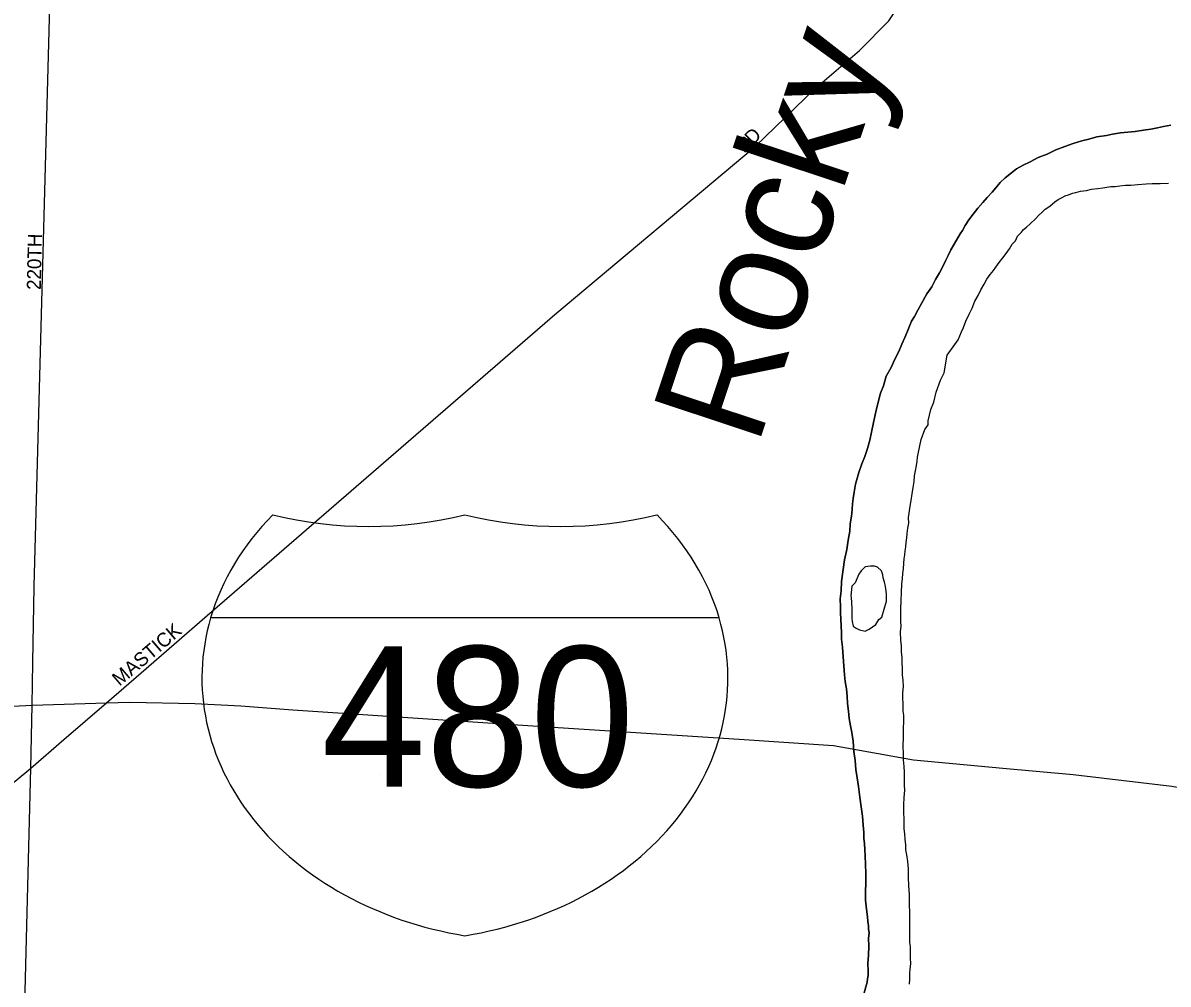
# Model space of a CAD drawing. Extents: x -561 to 1170, y 0 to 846.
# Drawn here: x 115.96 to 126.99, y 211.77 to 221.02 of the extents above; entities that cross this region are included whole.
import ezdxf

# ---------------------------------------------------------------- set-up
doc = ezdxf.new("R2010")
doc.units = 0
for name, color, linetype in [('GM_X_City_Street', 7, 'Continuous'), ('GM_X_City_Street_Text', 7, 'Continuous'), ('GM_X_Interstate_Location', 7, 'Continuous'), ('GM_X_Interstate_Route', 7, 'Continuous'), ('GM_X_Interstate_Shield', 7, 'Continuous'), ('GM_X_Major_River', 7, 'Continuous'), ('GM_X_Major_River_Text', 7, 'Continuous')]:
    doc.layers.add(name, color=color, linetype=linetype)

msp = doc.modelspace()

# ---------------------------------------------------------------- linework, layer by layer
at = {"layer": 'GM_X_City_Street'}
for points in [[(116.071, 215.595), (116.452, 229.741), (116.491, 231.039), (116.448, 231.209)], [(117.737, 215.314), (121.082, 218.211), (123.012, 219.827), (123.587, 220.387), (124.016, 220.753), (124.298, 221.039), (124.521, 221.379), (124.761, 221.789), (125.169, 222.415), (125.485, 222.833), (125.94, 223.24), (126.531, 223.757), (126.787, 223.943)], [(116.057, 214.865), (116.071, 215.589), (116.071, 215.595)], [(117.1, 214.762), (117.737, 215.314), (117.737, 215.314)], [(116.038, 213.843), (116.05, 214.449), (116.057, 214.861), (116.057, 214.865)], [(116.357, 214.118), (116.766, 214.473), (117.1, 214.762), (117.1, 214.762)], [(116.038, 213.843), (116.357, 214.118), (116.357, 214.118)], [(107.912, 208.655), (108.898, 209.185), (109.975, 209.776), (111.966, 210.908), (113.048, 211.474), (113.955, 212.017), (115.111, 212.997), (115.886, 213.719), (116.038, 213.843)], [(115.967, 211.064), (116.038, 213.843)]]:
    msp.add_lwpolyline(points, dxfattribs=at)
at = {"layer": 'GM_X_Interstate_Route'}
for points in [[(109.61, 213.187), (109.745, 213.235), (110.052, 213.346), (111.576, 213.815), (112.111, 213.979), (112.489, 214.094), (112.787, 214.155), (113.084, 214.194), (113.425, 214.244), (113.863, 214.289), (114.382, 214.334), (115.242, 214.408), (116.05, 214.449), (116.766, 214.473), (116.99, 214.48), (117.617, 214.465), (118.061, 214.445), (118.559, 214.404), (121.014, 214.243)], [(121.014, 214.243), (122.857, 214.122)], [(122.857, 214.122), (123.765, 214.062), (124.534, 213.923), (125.396, 213.844)], [(125.396, 213.844), (126.072, 213.782), (127.02, 213.67), (127.943, 213.499), (128.481, 213.369), (129.006, 213.216), (129.464, 213.053), (130.319, 212.721), (132.188, 211.906)]]:
    msp.add_lwpolyline(points, dxfattribs=at)
at = {"layer": 'GM_X_Interstate_Shield'}
msp.add_line((122.664, 215.29), (117.769, 215.29), dxfattribs=at)
msp.add_line((122.664, 215.29), (117.769, 215.29), dxfattribs=at)
for centre, start_param, end_param in [((120.849, 214.711), 2.47259, 2.911027), ((119.292, 218.702), 4.415841, 5.008937), ((121.141, 218.702), 4.415841, 5.008937), ((119.584, 214.711), 0.230566, 0.669003), ((120.849, 214.711), 2.911027, 4.511031), ((119.584, 214.711), 4.913747, 6.513751)]:
    msp.add_ellipse(centre, major_axis=(3.164, 0), ratio=0.8, start_param=start_param, end_param=end_param, dxfattribs=at)
at = {"layer": 'GM_X_Major_River'}
for points in [[(124.544, 218.192), (124.575, 218.252), (124.612, 218.318), (124.664, 218.411), (124.712, 218.477), (124.748, 218.548), (124.785, 218.613), (124.816, 218.674), (124.843, 218.728), (124.869, 218.778), (124.895, 218.832), (124.926, 218.887), (124.984, 218.986), (125.005, 219.019), (125.031, 219.068), (125.068, 219.123), (125.11, 219.178), (125.153, 219.233), (125.201, 219.288), (125.243, 219.338), (125.291, 219.387), (125.328, 219.431), (125.37, 219.481), (125.418, 219.525), (125.477, 219.575), (125.525, 219.614), (125.589, 219.648), (125.659, 219.681), (125.734, 219.721), (125.82, 219.755), (125.906, 219.795), (125.992, 219.829), (126.073, 219.857), (126.154, 219.881), (126.224, 219.898), (126.299, 219.921), (126.391, 219.934), (126.451, 219.946), (126.526, 219.958), (126.597, 219.965), (126.667, 219.972), (126.748, 219.984), (126.818, 219.996), (126.883, 220.008), (126.942, 220.02), (127.013, 220.033)], [(127.013, 220.033), (126.942, 220.02), (126.883, 220.008), (126.818, 219.996), (126.748, 219.984), (126.667, 219.972), (126.597, 219.965), (126.526, 219.958), (126.451, 219.946), (126.391, 219.934), (126.299, 219.921), (126.224, 219.898), (126.154, 219.881), (126.073, 219.857), (125.992, 219.829), (125.906, 219.795), (125.82, 219.755), (125.734, 219.721), (125.659, 219.681), (125.589, 219.648), (125.525, 219.614), (125.477, 219.575), (125.418, 219.525), (125.37, 219.481), (125.328, 219.431), (125.291, 219.387), (125.243, 219.338), (125.201, 219.288), (125.153, 219.233), (125.11, 219.178), (125.068, 219.123), (125.031, 219.068), (125.005, 219.019), (124.984, 218.986), (124.926, 218.887), (124.895, 218.832), (124.869, 218.778), (124.843, 218.728), (124.816, 218.674), (124.785, 218.613), (124.748, 218.548), (124.712, 218.477), (124.664, 218.411), (124.612, 218.318), (124.575, 218.252), (124.544, 218.192)], [(124.439, 213.925), (124.438, 213.985), (124.436, 214.055), (124.44, 214.142), (124.439, 214.223), (124.443, 214.299), (124.442, 214.353), (124.436, 214.391), (124.435, 214.418), (124.434, 214.467), (124.433, 214.516), (124.432, 214.57), (124.437, 214.629), (124.436, 214.689), (124.429, 214.743), (124.428, 214.803), (124.427, 214.857), (124.426, 214.906), (124.42, 214.965), (124.418, 215.025), (124.412, 215.073), (124.411, 215.155), (124.415, 215.209), (124.414, 215.252), (124.413, 215.306), (124.412, 215.377), (124.424, 215.615), (124.428, 215.67), (124.433, 215.719), (124.437, 215.762), (124.442, 215.816), (124.446, 215.86), (124.451, 215.898), (124.456, 215.936), (124.46, 215.974), (124.465, 216.017), (124.47, 216.061), (124.474, 216.104), (124.479, 216.153), (124.489, 216.202), (124.488, 216.256), (124.492, 216.299), (124.502, 216.365), (124.512, 216.419), (124.521, 216.484), (124.531, 216.544), (124.541, 216.604), (124.545, 216.658), (124.555, 216.707), (124.565, 216.756), (124.57, 216.799), (124.574, 216.837), (124.579, 216.87), (124.609, 217.006), (124.645, 217.104), (124.677, 217.148), (124.676, 217.186), (124.701, 217.295), (124.732, 217.366), (124.752, 217.464), (124.794, 217.579), (124.83, 217.65), (124.859, 217.818), (124.933, 217.923), (124.965, 217.967), (124.981, 218.005), (124.996, 218.043), (125.017, 218.087), (125.038, 218.147), (125.069, 218.213), (125.1, 218.273), (125.126, 218.338), (125.158, 218.393), (125.184, 218.448), (125.215, 218.502), (125.241, 218.552), (125.273, 218.596), (125.305, 218.634), (125.326, 218.667), (125.358, 218.711), (125.395, 218.755), (125.426, 218.799), (125.458, 218.843), (125.484, 218.887), (125.516, 218.92), (125.537, 218.964), (125.574, 219.003), (125.595, 219.03), (125.622, 219.052), (125.659, 219.085), (125.713, 219.135), (125.739, 219.163), (125.771, 219.191), (125.803, 219.224), (125.846, 219.252), (125.894, 219.296), (125.926, 219.318), (125.953, 219.329), (126.001, 219.357), (126.028, 219.363), (126.066, 219.38)], [(124.439, 213.925), (124.438, 213.985), (124.436, 214.055), (124.44, 214.142), (124.439, 214.223), (124.443, 214.299), (124.442, 214.353), (124.436, 214.391), (124.435, 214.418), (124.434, 214.467), (124.433, 214.516), (124.432, 214.57), (124.437, 214.629), (124.436, 214.689), (124.429, 214.743), (124.428, 214.803), (124.427, 214.857), (124.426, 214.906), (124.42, 214.965), (124.418, 215.025), (124.412, 215.073), (124.411, 215.155), (124.415, 215.209), (124.414, 215.252), (124.413, 215.306), (124.412, 215.377), (124.424, 215.615), (124.428, 215.67), (124.433, 215.719), (124.437, 215.762), (124.442, 215.816), (124.446, 215.86), (124.451, 215.898), (124.456, 215.936), (124.46, 215.974), (124.465, 216.017), (124.47, 216.061), (124.474, 216.104), (124.479, 216.153), (124.489, 216.202), (124.488, 216.256), (124.492, 216.299), (124.502, 216.365), (124.512, 216.419), (124.521, 216.484), (124.531, 216.544), (124.541, 216.604), (124.545, 216.658), (124.555, 216.707), (124.565, 216.756), (124.57, 216.799), (124.574, 216.837), (124.579, 216.87), (124.609, 217.006), (124.645, 217.104), (124.677, 217.148), (124.676, 217.186), (124.701, 217.295), (124.732, 217.366), (124.752, 217.464), (124.794, 217.579), (124.83, 217.65), (124.859, 217.818), (124.933, 217.923), (124.965, 217.967), (124.981, 218.005), (124.996, 218.043), (125.017, 218.087), (125.038, 218.147), (125.069, 218.213), (125.1, 218.273), (125.126, 218.338), (125.158, 218.393), (125.184, 218.448), (125.215, 218.502), (125.241, 218.552), (125.273, 218.596), (125.305, 218.634), (125.326, 218.667), (125.358, 218.711), (125.395, 218.755), (125.426, 218.799), (125.458, 218.843), (125.484, 218.887), (125.516, 218.92), (125.537, 218.964), (125.574, 219.003), (125.595, 219.03), (125.622, 219.052), (125.659, 219.085), (125.713, 219.135), (125.739, 219.163), (125.771, 219.191), (125.803, 219.224), (125.846, 219.252), (125.894, 219.296), (125.926, 219.318), (125.953, 219.329), (126.001, 219.357), (126.028, 219.363), (126.066, 219.38)], [(126.066, 219.38), (126.098, 219.386), (126.141, 219.398), (126.201, 219.405), (126.249, 219.416), (126.309, 219.423), (126.357, 219.429), (126.395, 219.436), (126.433, 219.442), (126.476, 219.442), (126.52, 219.449), (126.574, 219.455), (126.628, 219.456), (126.693, 219.463), (126.774, 219.47), (126.833, 219.471), (126.909, 219.472), (126.991, 219.474)], [(126.066, 219.38), (126.098, 219.386), (126.141, 219.398), (126.201, 219.405), (126.249, 219.416), (126.309, 219.423), (126.357, 219.429), (126.395, 219.436), (126.433, 219.442), (126.476, 219.442), (126.52, 219.449), (126.574, 219.455), (126.628, 219.456), (126.693, 219.463), (126.774, 219.47), (126.833, 219.471), (126.909, 219.472), (126.991, 219.474)], [(124.053, 211.658), (124.089, 211.783), (124.093, 211.816), (124.098, 211.849), (124.097, 211.892), (124.096, 211.962), (124.1, 212.044), (124.104, 212.13), (124.102, 212.206), (124.107, 212.255), (124.101, 212.298), (124.1, 212.325), (124.094, 212.369), (124.093, 212.412), (124.087, 212.461), (124.08, 212.515), (124.074, 212.574), (124.072, 212.655), (124.076, 212.737), (124.075, 212.829), (124.073, 212.921), (124.071, 212.997), (124.065, 213.062), (124.064, 213.116), (124.057, 213.17), (124.056, 213.224), (124.05, 213.294), (124.043, 213.381), (124.03, 213.473), (124.018, 213.565), (124.005, 213.667), (123.992, 213.749), (123.98, 213.83), (123.973, 213.916), (123.961, 214.003), (123.953, 214.105), (123.941, 214.186), (123.929, 214.251), (123.917, 214.321), (123.91, 214.392), (123.898, 214.467), (123.897, 214.538), (123.89, 214.608), (123.878, 214.678), (123.871, 214.743), (123.864, 214.83), (123.857, 214.916), (123.85, 215.008), (123.843, 215.084), (123.842, 215.149), (123.833, 215.339), (123.832, 215.398), (123.83, 215.474), (123.84, 215.55), (123.843, 215.642), (123.872, 215.849), (123.892, 215.947), (123.906, 216.039), (123.921, 216.126), (123.925, 216.196), (123.935, 216.251), (123.94, 216.294), (123.944, 216.338), (123.949, 216.387), (123.953, 216.441), (123.963, 216.501), (123.978, 216.577), (124.008, 216.691), (124.039, 216.773), (124.065, 216.844), (124.091, 216.92), (124.116, 217.002), (124.131, 217.078), (124.151, 217.171), (124.171, 217.274), (124.196, 217.367), (124.216, 217.454), (124.247, 217.525), (124.273, 217.617), (124.32, 217.7), (124.356, 217.782), (124.393, 217.853), (124.424, 217.924), (124.45, 217.989), (124.476, 218.049), (124.497, 218.099), (124.517, 218.148), (124.544, 218.192)], [(124.544, 218.192), (124.517, 218.148), (124.497, 218.099), (124.476, 218.049), (124.45, 217.989), (124.424, 217.924), (124.393, 217.853), (124.356, 217.782), (124.32, 217.7), (124.273, 217.617), (124.247, 217.525), (124.216, 217.454), (124.196, 217.367), (124.171, 217.274), (124.151, 217.171), (124.131, 217.078), (124.116, 217.002), (124.091, 216.92), (124.065, 216.844), (124.039, 216.773), (124.008, 216.691), (123.978, 216.577), (123.963, 216.501), (123.953, 216.441), (123.949, 216.387), (123.944, 216.338), (123.94, 216.294), (123.935, 216.251), (123.925, 216.196), (123.921, 216.126), (123.906, 216.039), (123.892, 215.947), (123.872, 215.849), (123.843, 215.642), (123.84, 215.55), (123.83, 215.474), (123.832, 215.398), (123.833, 215.339), (123.842, 215.149), (123.843, 215.084), (123.85, 215.008), (123.857, 214.916), (123.864, 214.83), (123.871, 214.743), (123.878, 214.678), (123.89, 214.608), (123.897, 214.538), (123.898, 214.467), (123.91, 214.392), (123.917, 214.321), (123.929, 214.251), (123.941, 214.186), (123.953, 214.105), (123.961, 214.003), (123.973, 213.916), (123.98, 213.83), (123.992, 213.749), (124.005, 213.667), (124.018, 213.565), (124.03, 213.473), (124.043, 213.381), (124.05, 213.294), (124.056, 213.224), (124.057, 213.17), (124.064, 213.116), (124.065, 213.062), (124.071, 212.997), (124.073, 212.921), (124.075, 212.829), (124.076, 212.737), (124.072, 212.655), (124.074, 212.574), (124.08, 212.515), (124.087, 212.461), (124.093, 212.412), (124.094, 212.369), (124.1, 212.325), (124.101, 212.298), (124.107, 212.255), (124.102, 212.206), (124.104, 212.13), (124.1, 212.044), (124.096, 211.962), (124.097, 211.892), (124.098, 211.849), (124.093, 211.816), (124.089, 211.783), (124.053, 211.658)], [(124.068, 215.782), (124.031, 215.743), (124.01, 215.71), (123.974, 215.628), (123.942, 215.595), (123.933, 215.503), (123.934, 215.49)], [(124.068, 215.782), (124.031, 215.743), (124.01, 215.71), (123.974, 215.628), (123.942, 215.595), (123.933, 215.503), (123.934, 215.49)], [(123.934, 215.49), (123.94, 215.379), (123.941, 215.33), (123.942, 215.286), (123.943, 215.254), (123.954, 215.211), (123.982, 215.19), (124.015, 215.174), (124.069, 215.164), (124.107, 215.181), (124.139, 215.204), (124.171, 215.226), (124.202, 215.275), (124.229, 215.297), (124.275, 215.45), (124.274, 215.52), (124.267, 215.574), (124.261, 215.607), (124.255, 215.634), (124.244, 215.677), (124.238, 215.704), (124.226, 215.742), (124.188, 215.779), (124.16, 215.789), (124.122, 215.788), (124.068, 215.782)], [(123.934, 215.49), (123.94, 215.379), (123.941, 215.33), (123.942, 215.286), (123.943, 215.254), (123.954, 215.211), (123.982, 215.19), (124.015, 215.174), (124.069, 215.164), (124.107, 215.181), (124.139, 215.204), (124.171, 215.226), (124.202, 215.275), (124.229, 215.297), (124.275, 215.45), (124.274, 215.52), (124.267, 215.574), (124.261, 215.607), (124.255, 215.634), (124.244, 215.677), (124.238, 215.704), (124.226, 215.742), (124.188, 215.779), (124.16, 215.789), (124.122, 215.788), (124.068, 215.782)], [(124.026, 215.77), (124.025, 215.77)], [(124.026, 215.77), (124.025, 215.77)], [(124.495, 211.764), (124.5, 211.813), (124.499, 211.867), (124.503, 211.911), (124.508, 211.959), (124.507, 212.019), (124.506, 212.073), (124.505, 212.127), (124.499, 212.165), (124.498, 212.203), (124.499, 212.447), (124.497, 212.539), (124.496, 212.626), (124.489, 212.712), (124.487, 212.793), (124.486, 212.875), (124.479, 212.945), (124.472, 213.01), (124.46, 213.058), (124.46, 213.107), (124.453, 213.161), (124.452, 213.21), (124.446, 213.259), (124.445, 213.302), (124.444, 213.351), (124.443, 213.421), (124.442, 213.492), (124.446, 213.562), (124.45, 213.633), (124.449, 213.681), (124.448, 213.719), (124.447, 213.757), (124.447, 213.806), (124.446, 213.86), (124.439, 213.925)], [(124.495, 211.764), (124.5, 211.813), (124.499, 211.867), (124.503, 211.911), (124.508, 211.959), (124.507, 212.019), (124.506, 212.073), (124.505, 212.127), (124.499, 212.165), (124.498, 212.203), (124.499, 212.447), (124.497, 212.539), (124.496, 212.626), (124.489, 212.712), (124.487, 212.793), (124.486, 212.875), (124.479, 212.945), (124.472, 213.01), (124.46, 213.058), (124.46, 213.107), (124.453, 213.161), (124.452, 213.21), (124.446, 213.259), (124.445, 213.302), (124.444, 213.351), (124.443, 213.421), (124.442, 213.492), (124.446, 213.562), (124.45, 213.633), (124.449, 213.681), (124.448, 213.719), (124.447, 213.757), (124.447, 213.806), (124.446, 213.86), (124.439, 213.925)]]:
    msp.add_lwpolyline(points, dxfattribs=at)

# ---------------------------------------------------------------- texts
at = {"layer": 'GM_X_City_Street_Text'}
for s, rotation, p in [('D', 44.1143, (122.987, 219.835)), ('R', 41.692, (122.903, 219.759)), ('220TH', 88.8315, (116.134, 218.446)), ('MASTICK', 40.5029, (116.892, 214.627))]:
    msp.add_text(s, height=0.135, rotation=rotation, dxfattribs=at).set_placement(p)
at = {"layer": 'GM_X_Interstate_Location'}
for s in ['-', '.', ',']:
    msp.add_text(s, height=0.0027, dxfattribs=at).set_placement((120.216, 214.339))
msp.add_text('480', height=0.0027, rotation=0, dxfattribs=at).set_placement((119.391, 213.78))
at = {"layer": 'GM_X_Interstate_Shield'}
msp.add_text('480', height=1.35, dxfattribs=at).set_placement((118.836, 213.666))
at = {"layer": 'GM_X_Major_River_Text'}
msp.add_text('Rocky', height=1.0807, rotation=71.5914, dxfattribs=at).set_placement((123.032, 216.927))

doc.saveas('drawing.dxf')
